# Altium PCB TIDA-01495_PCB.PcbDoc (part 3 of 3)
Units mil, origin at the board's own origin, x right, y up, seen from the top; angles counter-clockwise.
Board outline 7283.46 x 4330.71 mil, 2 copper layers (Top Layer, Bottom Layer), stack 64.6 mil thick; 242 components, 114 nets, 539 pads, 127 vias.
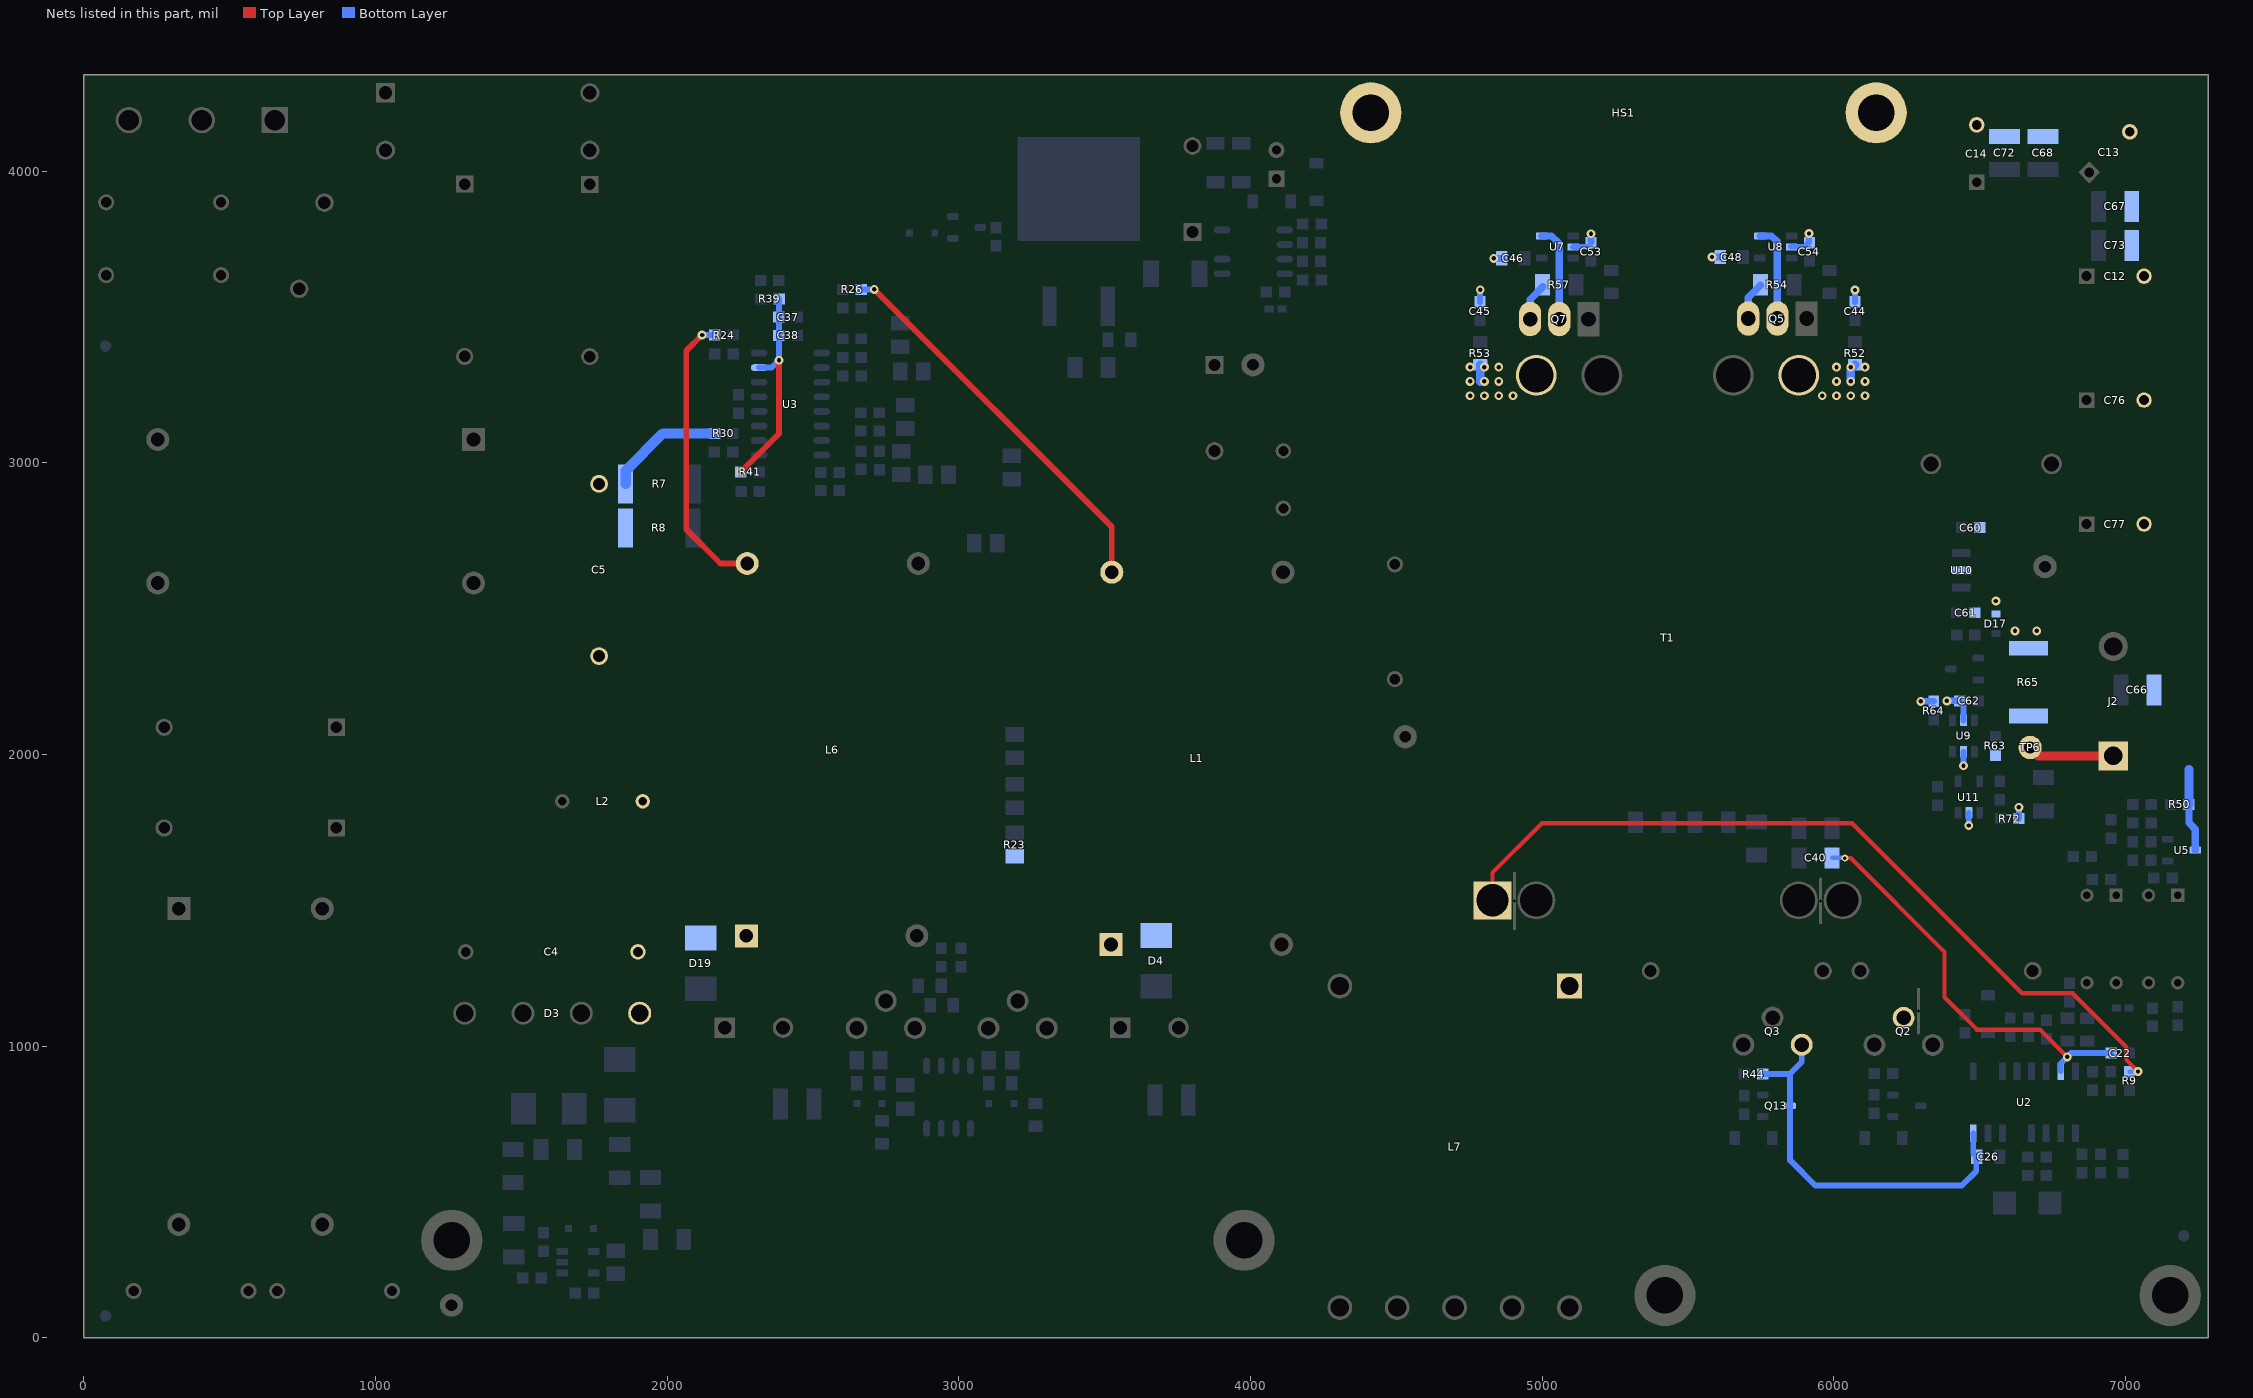
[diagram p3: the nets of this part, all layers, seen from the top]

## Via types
v1: diameter 30, hole 15, Top Layer to Bottom Layer, 109 vias
v2: diameter 20, hole 10, Top Layer to Bottom Layer, 16 vias
v3: diameter 24, hole 12, Top Layer to Bottom Layer, 2 vias

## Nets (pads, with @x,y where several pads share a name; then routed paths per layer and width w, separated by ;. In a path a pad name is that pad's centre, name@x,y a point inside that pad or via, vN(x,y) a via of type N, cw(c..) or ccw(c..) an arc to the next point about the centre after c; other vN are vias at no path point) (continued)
RET: J2.1 R63.1 R65.2 TP6.1 | length 297.1
  Top Layer w30: TP6.1@6672.83,2023.89 6701.72,1995 J2.1@6958,1995
SGND: C12.2 C13.2 C14.2 C44.1 C45.1 C46.2 C48.2 C53.2 C54.2 C60.2 C61.2 C62.2 C66.2 C67.2 C68.2 C72.2 C73.2 C76.2 C77.2 D17.2 HS1.1 HS1.2 Q5.3 Q7.3 R50.1 R54.2 R57.2 R64.1 R65.1 R72.1 U5.3 U7.2 U8.2 U9.2 U9.5 U10.2 U11.2 | length 1149.6
  Bottom Layer w20: v1(4787.47,3592.79) C45.1@4787.51,3551.52 ; U7.2@5106.37,3740.06 C53.2@5152.55,3740.06 ; U8.2@5853.68,3740.59 5899.86,3740.59 5914.92,3755.66 v1(5914.92,3785.88) ; C44.1@6072.63,3551.41 6072.78,3551.56 v1(6072.78,3592.14) ; v1(6444.73,1961.08) U9.2@6444.73,2009.36 ; v1(6462.82,1756.25) U11.2@6462.82,1799.63 ; R72.1@6634.5,1780 v1(6634.5,1819.4) ; C45.1@4787.51,3551.52 C45.1@4787.51,3551.52
  Bottom Layer w22: v1(6298.32,2181.88) R64.1@6342.6,2181.88 ; v1(6387.7,2183.57) C62.2@6432.04,2183.57 6444.73,2170.88 U9.5@6444.73,2117.63
  Bottom Layer w25: v1(4834.14,3700.57) C46.2@4862.03,3700.57 ; Q7.3@4958.88,3492.68 4958.88,3559.96 R57.2@5001.91,3603 ; C53.2@5167.61,3755.13 v1(5167.61,3785.35) ; v1(5582.5,3705.36) C48.2@5611.35,3705.36 ; Q5.3@5706.6,3494.47 5706.6,3566.62 R54.2@5748.88,3608.89 ; R50.1@7217.57,1828.83 7217.57,1765.55 7239.24,1743.87 U5.3@7239.24,1672
  Bottom Layer w30: R50.1@7217.57,1828.83 7217.57,1948.79
  other v1: 6620.98,2423.54 6695.53,2423.54 6555.7,2526.27
SW: C26.2 L7.1 Q2.2 Q3.3 Q13.3 R44.1 U2.16 | length 1330.1
  Bottom Layer w20: R44.1@5756.43,905.97 R44.1@5756.5,905.97 ; R44.1@5756.5,904 5848.22,904 5850.18,905.96 ; Q3.3@5890,1005 5890,945.78 5850.18,905.96 ; U2.16@6477.97,701.33 6477.97,632.66 C26.2@6489.63,621 ; C26.2@6488.2,614.43 6488.2,571.44 6438.71,521.95 5936.66,521.95 5850.18,608.43 Q13.3@5850.18,795.57 5850.18,905.96
VAC: C5.2 D4.2 D19.2 L1.1 L2.2 L6.1 R23.2
VCR: C22.1 C40.2 U2.7 | length 1393.6
  Top Layer w15: v3(6037.56,1645) 6057.67,1645 6379.61,1323.07 6379.61,1167.68 6490.56,1056.72 6706.97,1056.72 v1(6800.67,963.02)
  Bottom Layer w15: C40.2@5994.36,1645.3 6037.27,1645.3 v3(6037.56,1645)
  Bottom Layer w20: U2.7@6777.97,913.93 6777.97,940.32 v1(6800.67,963.02) 6813.65,976 C22.1@6950.5,976
VD1: Q7.2 R53.1 T1.13 U7.5 | length 385.9
  Bottom Layer w25: U7.5@4998.1,3777.47 5031.88,3777.47 5058.88,3750.48 Q7.2@5058.88,3492.68
  Bottom Layer w30: v1@4787.47,3278.79 4787.47,3334.91 R53.1@4787.51,3334.95
  other v1: 4753,3230 4802,3230 4851,3230 4900,3230 4753,3279 4802,3279 4851,3279 4753,3328 4802,3328 4851,3328
VD2: Q5.2 R52.1 T1.8 U8.5 | length 393.7
  Bottom Layer w20: Q5.2@5806.19,3493.21 Q5.2@5806.19,3493.36
  Bottom Layer w25: U8.5@5746.87,3777.4 5786.04,3777.4 5806.19,3757.25 Q5.2@5806.19,3493.36
  Bottom Layer w30: v1(6058,3279) 6058,3319.93 6072.78,3334.7 R52.1@6072.63,3334.85
  other v1: 5960,3230 6009,3230 6058,3230 6107,3230 6009,3279 6107,3279 6009,3328 6058,3328 6107,3328
VN: C4.2 C5.1 D3.4 R7.2 R8.2 R30.1 | length 403.4
  Bottom Layer w35: R7.2@1858.08,2927.3 1858.08,2973.24 1985.64,3100.8 R30.1@2162.72,3100.8
VREF: C37.1 C38.1 R39.1 R41.2 U3.15 | length 726.5
  Top Layer w20: v1(2252.82,2968.64) 2383.68,3099.5 v1(2383.68,3351.71)
  Bottom Layer w20: U3.15@2315.54,3326.17 2358.14,3326.17 v1(2383.68,3351.71) C38.1@2383.68,3436.5 C37.1@2383.68,3499.14 2383.95,3499.41 R39.1@2383.95,3562.07
X: R9.2 T1.1 | length 2785.3
  Top Layer w15: T1.1@4830,1500 4830,1594.87 4999.22,1764.08 6062.57,1764.08 6645.41,1181.24 6818.51,1181.24 7003.61,996.14 7003.61,952.39 v1(7043,913)
  Bottom Layer w15: R9.2@7014.06,912.54 7014.51,913 v1(7043,913)
ZCD1: L1.4 R26.2 | length 1351.8
  Top Layer w20: v1(2710.66,3594.32) 3524.65,2780.34 L1.4@3524.65,2624.76
  Bottom Layer w20: R26.2@2665.62,3594.32 v1(2710.66,3594.32)
ZCD2: L6.4 R24.1 | length 989.7
  Top Layer w20: v1(2120,3438) 2065.75,3383.75 2065.75,2771.79 2182.78,2654.76 L6.4@2274.65,2654.76
  Bottom Layer w20: v1(2120,3438) 2163.63,3438 R24.1@2163.67,3437.96
pads on no net: FID1.1 FID2.1 FID3.1 H1.0 H2.0 H3.0 H4.0 H5.0 H6.0 HS3.1 HS3.2 L7.6 L7.7 L7.8 L7.9 L7.10 U1.1 U1.8 U4.6

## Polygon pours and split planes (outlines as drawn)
PGND on Bottom Layer "Bottom Layer-NetC3_1" (solid, remove dead copper, pour order 320): 1153.7,435.61 1153.7,122.84 1206.84,69.7 1696.94,69.7 1724.67,97.43 1724.67,409.73 1686.47,447.94 1164.06,447.94 1153.71,437.58
RET on Bottom Layer "RET_L02_P318" (solid, remove dead copper, pour order 318): 6531.16,2011.21 6531.16,2015.91 6536.88,2021.63 6586.95,2021.63 6599.05,2033.73 6599.05,2158.74 6602.41,2162.1 6739.52,2162.1 6741.87,2159.75 6741.87,1991.38 6732.46,1981.97 6581.32,1981.97 6574.93,1975.59 6535.66,1975.59 6531.09,1980.15
SGND on Bottom Layer "SGND_L02_P316" (solid, remove dead copper, pour order 316): 6477.33,2794.24 6477.33,2662.33 6465,2650 6406.96,2650 6402.27,2645.31 6402.27,2614.25 6407.22,2609.3 6463.63,2609.3 6484.4,2588.52 6484.4,2535.86 6461.56,2513.02 6461.56,2464.49 6466.62,2459.43 6580.78,2459.43 6596.57,2443.64 6596.57,2296.67 6609.16,2284.08 6739.23,2284.08 6754.49,2299.34 6754.49,2392.65 6639.68,2507.46 6639.68,2785.64 6623.72,2801.6 6481.27,2801.6 6477.32,2797.65
PGND on Bottom Layer "PGND_L02_P276" (solid, remove dead copper, pour order 276): 3879.97,749.02 3762.75,749.02 3757.65,754.12 3756.08,755.69 3756.08,798.07 3756.08,876.55 3758.82,879.3 3765.49,885.97 3809.44,885.97 3876.95,885.97 3896.5,866.42 3896.5,765.54
PGND on Bottom Layer "PGND_L02_P274" (solid, remove dead copper, pour order 274): 2596.98,736.94 2479.76,736.94 2474.66,742.05 2473.09,743.61 2473.09,786 2473.09,864.48 2475.84,867.23 2482.51,873.9 2526.46,873.9 2593.96,873.9 2613.51,854.35 2613.51,753.47
VN on Bottom Layer "Bottom Layer-No Net 8" (solid, remove dead copper, pour order 268): 1731.09,2748.63 1778.3,2701.43 1882.01,2701.43 1891.98,2711.4 1891.98,2994.62 1885.33,3001.27 1758.35,3001.27 1731.09,2974.01
VAC on Bottom Layer "Bottom Layer-No Net 7" (solid, remove dead copper, pour order 266): 3533.76,1458.24 3562.13,1429.86 3721.99,1429.86 3730.37,1421.48 3730.37,1337.98 3727.32,1334.93 3592.51,1334.93 3568.08,1310.5 3562.38,1304.8 3465.47,1304.8 3275.25,1495.03 2472.42,1495.03 2300.65,1323.26 2052.66,1323.26 2030.88,1345.03 2030.88,1528.98 2015.79,1544.67 1886.39,1674.07 1886.39,2088.71 1733.37,2241.73 1733.37,2352.73 1752.26,2371.62 1859.32,2371.62 2049.66,2181.28 2049.66,1834.23 2202.54,1681.35 3310.65,1681.35 3485.79,1506.21
NetC6_1 on Bottom Layer "Bottom Layer-No Net 4" (solid, remove dead copper, pour order 256): 483.99,3812.17 1313.76,3812.17 1421.68,3704.24 1421.68,3302.5 1292.86,3173.67 1292.86,3037.85 1301.7,3029.01 1421.68,3029.01 1617.39,3224.71 1617.39,3617.05 1771.61,3771.27 1771.61,4091.38 1755.7,4107.29 1388.89,4107.29 1258.82,3977.22 480.24,3977.22 440.1,3937.07 440.1,3856.06
24V on Bottom Layer "Bottom Layer-No Net 3" (solid, remove dead copper, pour order 242): 6795.38,2285.4 6795.38,2402.09 6670.78,2525.96 6670.78,3111.21 6811.03,3251.45 6917.09,3251.45 6949.11,3219.43 6949.11,2552.23 7028.96,2472.38 7028.96,2166.11 7017.9,2155.04 6925.74,2155.04
NetC8_1 on Bottom Layer "Bottom Layer-No Net 2" (solid, remove dead copper, pour order 240): 5359.75,3356.39 5173.85,3356.39 5129.91,3312.45 5129.91,2624.39 5132.45,2621.85 6316.47,2621.85 6625.84,2931.22 6625.84,3161.31 6944.07,3479.54 6944.07,4013.91 6909.58,4048.4 6455.14,4048.4 6220.2,3813.45 6220.2,3267.44 6110.06,3157.31 5781.01,3157.31 5731.01,3207.3 5731.01,3324.27 5698.82,3356.47 5360.24,3356.47
SGND on Bottom Layer "Bottom Layer-No Net 1" (solid, remove dead copper, pour order 228): 7067.38,1904.19 7091.81,1879.76 7264.07,1879.76 7283.65,1899.34 7283.13,1950.89 7283.13,4253.01 7207.24,4328.9 6068.88,4328.9 6029.07,4289.09 6029.05,4231.23 6029.05,4124.1 6072.32,4080.83 6935.53,4080.83 6989.1,4027.27 6989.1,2581.03 7067.38,2502.74
NetC47_1 on Bottom Layer "Bottom Layer-No Net" (solid, remove dead copper, pour order 216): 1088.75,486.2 1312.06,709.51 1537.82,709.51 1574.1,745.79 1574.1,1104.13 1524.14,1154.09 1488.08,1154.09 1446.44,1112.44 1446.44,968.21 1400.79,922.56 1208.11,922.56 774.56,489.01 774.56,371.88 1017.44,129.01 1067.18,129.01 1088.75,150.58
390V on Bottom Layer "Bottom Layer-No Net 9" (solid, remove dead copper, pour order 282): 3641.27,1270.92 3617.4,1247.04 3431.44,1061.08 3431.44,634.94 3355.4,558.9 2364.26,558.9 2232.67,690.49 2232.67,1098.37 2232.67,1222.65 2213.21,1242.12 2061.08,1242.12 2055.54,1236.57 2055.54,1091.81 2099.9,1047.45 2099.9,516.16 2429.91,186.15 3345.37,186.15 3582.24,423.02 3582.24,1027.05 3713.36,1158.17 3886.54,1158.17 3956.45,1227.46 3956.45,1736.68 3867.72,1825.41 3867.72,3102.01 3943.54,3177.82 3943.54,3343.41 3918.65,3368.29 3715.05,3368.29 3665,3318.24 3665,3064.87 3665,1726.4 3711.91,1679.5 3791.78,1599.62 3791.78,1279.66 3783.03,1270.92
PGND on Bottom Layer "Bottom Layer-No Net 10" (solid, remove dead copper, pour order 284): 6301.05,1021.31 6301.05,1029.05 6308.73,1036.73 6308.73,1201.75 6301.05,1209.43 6301.05,1306.5 6263.09,1344.46 6092.26,1344.46 5968.34,1468.38 5968.34,1531.73 6008.03,1571.42 6341.73,1571.42 6641.94,1269.61 6708.92,1269.61 6738.53,1240.01 6879.52,1240.01 6921.62,1197.9 6921.62,1081.6 6912.72,1072.69 6422.53,1072.69 6380.21,1030.38 6380.21,966.2 6357.38,943.37 6321.8,943.37 6301.05,964.12
PGND on Bottom Layer "PGND_L02_P286" (solid, remove dead copper, pour order 286): 2040.66,3624.28 2040.66,2977.46 2040.66,2707.35 2117.46,2630.54 2155.86,2592.14 2578.29,2592.14 3016.72,2592.14 3452.92,3028.34 3452.92,3612.39 3384.19,3681.12 2243.64,3681.12 2097.49,3681.12
390V on Bottom Layer "Bottom Layer-No Net 11" (solid, remove dead copper, pour order 288): 5727,1108.05 5774.77,1060.28 5806.27,1060.28 5827.74,1081.75 5827.74,1138.09 5069.05,1896.79 3894,1896.79 3840.46,1950.33 3840.46,1671.63 3893.29,1724.46 4979.51,1724.46 5340.65,1363.32 5340.65,1218.32 5450.93,1108.05
NetL7_2 on Bottom Layer "Bottom Layer-No Net 12" (solid, remove dead copper, pour order 300): 4254.1,1183.76 4291.63,1146.23 4827.86,1146.23 5052.01,1370.37 5052.01,1521.68 5007.16,1566.53 4953.63,1566.53 4913.66,1526.56 4913.66,1389.5 4811.94,1287.79 4290.56,1287.79 4254.1,1251.33
PGND on Bottom Layer "Bottom Layer-No Net 13" (solid, remove dead copper, pour order 302): 6646.3,1246.35 6646.3,765.55 6940.21,471.64 7126.86,471.64 7178.95,523.73 7178.95,1163.79 7102.53,1240.21 7100.11,1240.21 6719.75,1240.21 6699.11,1260.85 6655.11,1260.85
NetC2_2 on Bottom Layer "Top Layer-No Net 11" (solid, remove dead copper, pour order 298): 6122.95,1229.95 6117.43,1224.44 5924.56,1224.44 5810.84,1338.16 5810.84,1510.21 5811.61,1541.21 5837.96,1567.56 5909.26,1567.56 5940.99,1535.84 5940.99,1411.92 6063.36,1289.55 6113.74,1289.55 6122.95,1280.33 6122.95,1244.74
VD1 on Bottom Layer "Top Layer-No Net 3" (solid, remove dead copper, pour order 322): 5017.39,3502.9 5017.39,3433.59 4944.13,3360.33 4757.56,3360.33 4733.01,3335.79 4733.01,3218.48 4769.27,3182.22 5051.87,3182.22 5103.59,3233.94 5103.59,3527.93 5078.18,3553.34 5038.73,3553.34 5017.39,3532
VD2 on Bottom Layer "Top Layer-No Net 3" (solid, remove dead copper, pour order 324): 5846.27,3431.8 5917.33,3360.73 6101.17,3360.73 6125.09,3336.82 6125.09,3220.77 6088.33,3184.01 5869.93,3184.01 5813.61,3184.01 5766.58,3231.03 5766.58,3531.36 5790.36,3555.13 5823.26,3555.13 5846.27,3532.12
NetD5_3 on Top Layer "Top Layer-No Net 9" (solid, remove dead copper, pour order 264): 2689.43,1161.85 2734.12,1117.17 2765.28,1117.17 2897.57,1249.46 2897.57,1265.96 2897.57,1396.13 2873.73,1419.97 2515.52,1419.97 2361.51,1265.96 2361.51,1048.12 2382.85,1026.77 2414,1026.77 2549.08,1161.85
NetD1_3 on Top Layer "Bottom Layer-No Net 6" (solid, pour order 262): 3307.74,1157.15 3257.44,1157.15 3217.25,1116.96 3186.26,1116.96 3163.69,1139.53 3163.69,1198.21 3186.18,1220.7 3231.42,1265.94 3606.23,1265.94 3729.15,1388.86 4128.32,1388.86 4149.8,1367.38 4149.79,1333.56 3843.73,1027.49 3739.08,1027.49 3609.42,1157.15
NetC4_1 on Top Layer "Top Layer-No Net 8" (solid, remove dead copper, pour order 260): 1237.75,1092.8 1268.37,1062.18 1344.19,1062.18 1379.57,1097.56 1379.57,1418.84 1675.77,1715.04 1675.77,1841.33 1652.25,1864.85 1590.93,1864.85 1237.75,1511.67
VN on Top Layer "Bottom Layer-No Net 5" (solid, remove dead copper, pour order 258): 1851.48,1106.64 1886.56,1071.56 1992.2,1071.56 2031.32,1110.68 2031.32,1460.68 2219.98,1649.34 2219.98,2381.87 1920.77,2681.08 1920.77,2918.91 1880.88,2958.8 1754.27,2958.8 1731.56,2936.08 1731.56,2609.92 2031.32,2310.16 2031.32,1736.58 1851.49,1556.75
NetC9_2 on Top Layer "Top Layer-No Net 6" (solid, remove dead copper, pour order 252): 216.79,4056.19 216.79,3776.87 695.03,3298.63 1460.84,3298.63 1492.1,3267.37 1492.1,3031.16 1273.3,2812.35 1273.3,2560.95 1310.81,2523.44 1410.83,2523.44 1448.34,2560.95 1448.34,2787.8 1789.05,3128.51 1789.05,3398.65 1751.54,3436.16 949.86,3436.16 721.68,3664.34 526.24,3664.34 376.21,3814.38 376.21,3998.02 455.13,4076.94 455.13,4193.74 427.29,4221.58 382.19,4221.58
NetFCL1_1 on Top Layer "Top Layer-No Net 5" (solid, remove dead copper, pour order 248): 605.98,4211.74 605.98,4095.32 671.21,4030.08 1089.73,4030.08 1140.91,4081.27 1140.91,4271.96 1099.76,4313.1 625.41,4313.1 605.91,4293.61
NetC10_1 on Top Layer "Top Layer-No Net 4" (solid, remove dead copper, pour order 246): 745.75,2449.76 745.75,1472.58 789.13,1429.19 853.75,1429.19 917.55,1493 917.55,2552.15 334.95,3134.75 231.77,3134.75 195.6,3098.58 195.6,2999.91 244.93,2950.58
NetC10_2 on Top Layer "Top Layer-No Net 1" (solid, remove dead copper, pour order 244): 187.75,2609.23 187.75,1479.6 238.07,1429.29 367.6,1429.29 406.89,1468.58 406.89,2510.41 277.68,2639.63 218.15,2639.63
VD2 on Top Layer "Top Layer-No Net 3" (solid, remove dead copper, pour order 238): 5846.27,3431.8 5917.33,3360.73 6101.3,3360.73 6125.09,3336.94 6125.09,3221.03 6088.07,3184.01 5869.93,3184.01 5813.61,3184.01 5766.58,3231.03 5766.58,3531.36 5790.36,3555.13 5823.26,3555.13 5846.27,3532.12
VD1 on Top Layer "Top Layer-No Net 3" (solid, remove dead copper, pour order 236): 5017.39,3502.9 5017.39,3433.59 4944.13,3360.33 4757.52,3360.33 4733.1,3335.91 4733.1,3218.53 4769.41,3182.22 5051.87,3182.22 5103.59,3233.94 5103.59,3527.93 5078.18,3553.34 5038.73,3553.34 5017.39,3532
NetC49_2 on Top Layer "Top Layer-No Net" (solid, remove dead copper, pour order 214): 140.93,312.79 140.93,148.19 158.83,130.29 182.44,130.29 275.76,223.6 767.7,715.54 1597.64,715.54 1749.17,867.07 1749.17,1129.92 1725.26,1153.83 1687.08,1153.83 1663.18,1129.94 1663.18,1011.05 1538.22,886.09 714.22,886.09
SW on Top Layer "Top Layer-No Net 10" (solid, remove dead copper, pour order 280): 5802.18,751.68 5928.22,877.72 5928.22,996.62 6046.17,1114.57 6168.64,1114.57 6223.65,1059.56 6255.74,1059.56 6277.57,1081.24 6277.57,1123.93 6233.5,1168 5999.77,1168 5851.86,1020.09 5851.86,1007.55 5851.86,944.96 5811.63,904.73 5534.96,904.73 5182.31,1257.38 5052.48,1257.38 5041.46,1246.36 5041.65,1179.37 5041.65,913.31 5203.28,751.68
PGND on Top Layer "Top Layer-No Net 12" (solid, remove dead copper, pour order 294): 7077.3,1265.07 7047.68,1294.69 6425.04,1294.69 6339.7,1209.36 6339.7,1062.12 6301.12,1023.54 6301.12,860.08 6025.57,584.53 5230.32,584.53 4869.6,945.25 3483.31,945.25 3329.02,1099.7 3285.77,1099.7 3264.3,1078.23 3264.3,1006.13 3226.71,968.54 3070.02,968.54 2915.55,1123.01 2857.45,1123.01 2812.05,1077.61 2812.05,992.1 2774.59,954.64 2089.09,954.64 1580.57,446.13 1219.07,446.13 1144.77,371.83 1144.77,126.5 1271.28,-0.01 6822.81,-0.01 7178.88,356.06 7178.88,1163.5
PGND on Top Layer "Top Layer-No Net 13" (solid, pour order 296): 4350.39,904.42 4463.1,1017.13 4463.1,1252.41 2864.91,2850.6 2146.95,2850.6 2101.27,2896.29 2101.27,3517.46 2289.24,3705.43 3353.97,3705.43 3514.08,3545.31 3514.08,3106.28 3648.38,2971.98 4059.01,2971.98 4730.53,2300.46 4730.53,1082.54 4906.45,906.62
SGND on Top Layer "Top Layer-No Net 2" (solid, remove dead copper, pour order 312): 6278.36,2584.14 6186.63,2492.4 6186.63,2003.62 6453.48,1736.76 7206.08,1736.76 7278.74,1809.42 7278.74,1824.23 7282.62,1824.23 7282.62,2467.79 7263.07,2487.34 7273.1,2497.37 7273.31,2736.59 7273.54,4290.83 7234.79,4329.57 4390.66,4329.57 4306.64,4245.56 4306.64,3921.82 4796.58,3431.88 4975.07,3431.88 4998.75,3455.57 4998.75,3545.55 5029.63,3576.42 5308.2,3576.42 5452.74,3431.88 5724.72,3431.88 5748.17,3455.32 5748.17,3555.95 5768.64,3576.42 6153.54,3576.42 6750.68,3576.42 6907.78,3419.32 6907.78,2752.8 6907.78,2658.55 6833.37,2584.14

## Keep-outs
Keep-Out Layer:
  circle w6: c2748.54,396.21 r80.51
  circle w6: c3200.55,396.21 r80.51
  circle w6: c5788.79,339.36 r80.51
  circle w6: c6237.55,339.14 r80.51
  circle w6: c5807.81,4160.11 r80.51
  circle w6: c5060.08,4158.33 r80.51
  lines w10: 0,0 0,4330.71 7283.46,4330.71 7283.46,0 0,0
  text ".Layer_Name" at 441.79,-892.66 h60

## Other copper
Top Layer:
  rectangle net NetC6_1: 1635.6,3913.99 1840,4312.79
  text ".Layer_Name" at 441.79,-892.66 h60
Bottom Layer:
  pour cut-out: 3949.37,3224.93 3913.56,3224.93 3772.18,3083.55 3772.18,2984.4 3896.12,2860.47 3921.82,2860.47 3971.46,2910.1 3971.46,3214.56 3960.96,3225.07 3952.62,3225.07
  text ".Layer_Name" at 441.79,-892.66 h60

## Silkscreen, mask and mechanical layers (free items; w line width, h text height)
Top Overlay:
  text "TIDA-01495-E1" at 4574.04,2699.95 h125 r90
  text ".Layer_Name" at 441.79,-892.66 h60
Bottom Overlay:
  lines w6: 1564.84,146.84 1589.87,146.84 1633.99,190.96 ; 2337.87,3358.12 2415,3358.12 ; 2594.85,3631.63 2594.85,3796.06 2636.19,3837.41 2675.66,3837.41 ; 2636.49,3258.56 2706.31,3258.56 ; 2704.09,3327.39 2742.42,3365.73 2742.42,3625.42 ; 4281.03,3767.99 4340.42,3767.99 4355.18,3753.22 ; 6602.35,1869.77 6626.43,1869.77 ; 6741.97,974.75 6758.78,974.75 6772.93,988.91 ; 6916.94,1538.35 6916.94,1492.12 ; 6979.18,1631.55 6943.75,1631.55 6923.08,1610.89 6790.21,1610.89 6769.95,1610.89 ; 7125.79,1540.7 7125.79,1487.84 ; 6769.95,1610.89 6769.95,1608.58 6776.62,1601.91 6776.62,1617.55 6769.95,1610.89 ; 6916.94,1492.12 6924.32,1499.5 6909.17,1499.5 6916.55,1492.12 6916.94,1492.12 ; 7125.79,1487.84 7125.79,1488.37 7132.22,1494.8 7118.83,1494.8 7125.79,1487.84
  text ".Layer_Name" at 441.79,-892.66 h60
Top Paste:
  text ".Layer_Name" at 441.79,-892.66 h60
Bottom Paste:
  text ".Layer_Name" at 441.79,-892.66 h60
Top Solder:
  text ".Layer_Name" at 441.79,-892.66 h60
  text ".Layer_Name" at 441.79,-892.66 h60
Bottom Solder:
  text ".Layer_Name" at 441.79,-892.66 h60
Drill Guide:
  text ".Layer_Name" at 441.79,-892.66 h60
M1 Board Outline:
  the board outline again, w10
M2 Board Dimensions:
  rectangle: -10.21,-434.17 364.79,-309.17
  rectangle: -135.21,-309.17 -10.21,-184.17
  lines w7: -135.21,-309.17 864.79,-309.17 ; -10.21,-434.17 -10.21,-184.17 ; 114.79,-434.17 114.79,-184.17 ; 364.79,-434.17 364.79,-184.17 ; 614.79,-434.17 614.79,-184.17 ; -135.21,-434.17 -135.21,-184.17 864.79,-184.17 864.79,-434.17 -135.21,-434.17
M3 3D STEP Top:
  text ".Layer_Name" at 441.79,-892.66 h60
M4 3D STEP Bottom:
  text ".Layer_Name" at 441.79,-892.66 h60
M5 Assembly Top:
  lines w10: -427.21,-964.33 6172.79,-964.33 ; -427.21,-761 6174.79,-761 ; -427.21,-557.67 -427.21,-1167.67 3577.79,-1167.67 6174.79,-1167.67 6174.79,-557.67 -426.71,-557.67 -426.71,-1167.67 1148.79,-1167.67 ; 2037.79,-1167.67 2037.79,-557.67 ; 3304.79,-761 3304.79,-557.67 ; 4144.79,-761 4144.79,-557.67 ; 4766.79,-1174.17 4766.79,-971.33
  text "COMPONENTS MARKED 'DNP' SHOULD NOT BE POPULATED." at 1018.29,-352.67 h60
  text "ASSEMBLY VARIANT:" at 1017.79,-468.17 h60
  text ".VariantName" at 2053.79,-468.17 h60
  text "PCB VIEWED FROM TOP SIDE" at -363.71,-689.83 h60
  text "BOARD #:" at 2112.79,-689.83 h60
  text ".PRJ_Number" at 2658.29,-689.83 h60
  text "REV:" at 3502.79,-689.83 h60
  text ".PCB_Rev" at 3794.29,-689.83 h60
  text "SVN REV:" at 4340.79,-689.83 h60
  text ".VersionControl_RevNumber" at 4846.79,-689.83 h60
  text "LAYER NAME =" at -363.71,-892.66 h60
  text "TID #:" at 2112.79,-893.17 h60
  text ".TID" at 2658.29,-893.17 h60
  text ".layer_Name" at 432.79,-895.17 h60
  text "PLOT NAME =" at -363.71,-1098.5 h60
  text ".plot_File_Name" at 441.79,-1098.5 h60
  text "GENERATED    :" at 2114.79,-1098.5 h60
  text ".Print_Date" at 2984.29,-1098.5 h60
  text ".Print_Time" at 3713.29,-1098.5 h60
  text "TEXAS INSTRUMENTS" at 4977.79,-1098.5 h60
M6 Assembly Bottom:
  lines w10: -427.71,-761.5 6174.29,-761.5 ; -425.71,-964.83 6174.29,-964.83 ; 980.29,-1174.67 980.29,-971.83 ; 1602.29,-761.5 1602.29,-558.17 ; 2442.29,-761.5 2442.29,-558.17 ; 3709.29,-1168.17 3709.29,-558.17 ; 4598.29,-1168.17 6173.79,-1168.17 6173.79,-558.17 -427.71,-558.17 -427.71,-1168.17 2169.29,-1168.17 6174.29,-1168.17 6174.29,-558.17
  text "COMPONENTS MARKED 'DNP' SHOULD NOT BE POPULATED." at 5966.79,-352.17 h60
  text ".VariantName" at 4922.79,-468.17 h60
  text "ASSEMBLY VARIANT:" at 5961.79,-468.17 h60
  text ".VersionControl_RevNumber" at 900.29,-690.33 h60
  text "SVN REV:" at 1406.29,-690.33 h60
  text ".PCB_Rev" at 1952.79,-690.33 h60
  text "REV:" at 2244.29,-690.33 h60
  text ".PRJ_Number" at 3088.79,-690.33 h60
  text "BOARD #:" at 3634.29,-690.33 h60
  text "PCB VIEWED FROM BOTTOM SIDE" at 6110.79,-690.33 h60
  text "LAYER NAME =" at 6110.79,-886.57 h60
  text ".TID" at 3088.79,-893.67 h60
  text "TID #:" at 3634.29,-893.67 h60
  text ".layer_Name" at 5288.79,-895.17 h60
  text "TEXAS INSTRUMENTS" at 769.29,-1099 h60
  text ".Print_Time" at 2033.79,-1099 h60
  text ".Print_Date" at 2762.79,-1099 h60
  text "GENERATED    :" at 3632.29,-1099 h60
  text ".plot_File_Name" at 5305.29,-1099 h60
  text "PLOT NAME =" at 6110.79,-1099 h60
M9 Title Sheet:
  drawing of 57 lines, arcs and shapes, not listed
  text "1" at 604.63,8002.33 h70
  text "2" at 3100.29,8002.33 h70
  text "3" at 5589.64,8002.33 h70
  text "4" at 8096.3,8002.33 h70
  text "5" at 10595.29,8002.33 h70
  text "6" at 13100.29,8002.33 h70
  text "A" at -551.71,6859.33 h70
  text "A" at 14248.29,6859.33 h70
  text "B" at -551.71,4479.33 h70
  text "B" at 14248.29,4479.33 h70
  text "C" at -551.71,2104.33 h70
  text "C" at 14248.29,2104.33 h70
  text "PROJECT TITLE:" at 11208.29,243.33 h45
  text ".PRJ_Title" at 11258.29,110.01 h60
  text "DESIGNED FOR:" at 11208.29,-57.67 h45
  text ".PRJ_Customer" at 11258.29,-197.67 h70
  text "D" at -551.71,-265.67 h70
  text "D" at 14248.29,-265.67 h70
  text "FILE NAME:" at 11208.29,-357.67 h45
  text ".PCB_File_Name_No_Path" at 11258.29,-477.67 h70
  text "Texas Instruments (TI) and/or its licensors do not warrant the accuracy or completeness of this specification" at 6238.79,-639.5 h45
  text "ENGINEER:" at 11208.29,-647.67 h45
  text "LAYOUT BY:" at 12713.29,-647.67 h45
  text "or any information contained therein. TI and/or its licensors do not warrant that this design will meet" at 6193.81,-752.17 h45
  text ".PRJ_Engineer" at 11258.29,-802.66 h70
  text ".PCB_Layout" at 12763.79,-802.66 h70
  text "the specifications, will be suitable for your application or fit for any particular purpose, or will operate in" at 6193.81,-864.84 h45
  text "ALTIUM DESIGNER VERSION:" at 12713.29,-957.67 h45
  text "an implementation. TI and/or its licensors do not warrant that the design is production worthy. You should" at 6193.81,-977.5 h45
  text "completely validate and test your design implementation to confirm the system functionality for your application." at 6238.79,-1090.17 h45
  text ".print_Scale" at 11258.29,-1090.99 h70
  text ".Application_BuildNumber" at 12763.79,-1090.99 h70
  text "1" at 604.63,-1297.67 h70
  text "2" at 3100.29,-1297.67 h70
  text "3" at 5589.64,-1297.67 h70
  text "4" at 8096.3,-1297.67 h70
  text "5" at 10595.29,-1297.67 h70
  text "6" at 13100.29,-1297.67 h70
M10 Fab Notes:
  drawing of 191 lines, arcs and shapes, not listed
  text "DESIGN INFORMATION" at 12251.81,6651.83 h60
  text "(REFER ALSO ARRAY/PANEL PROFILING INFORMATION)" at 11890.25,6490.12 h60
  text "BOARD SIZE" at 11204.25,6485.83 h60
  text "X" at 12172.25,6358.01 h60
  text "110MM" at 12407.79,6350.83 h60
  text "185MM" at 11720.29,6347.35 h60
  text "Number of Layers :" at 11622.25,6250.83 h60
  text "2" at 12717.06,6240.84 h60
  text "MIN. TRACK WIDTH:" at 11622.25,6111.83 h60
  text "10" at 12691.79,6112.23 h60
  text "MIL" at 12873.25,6111.83 h60
  text "5" at 12702.68,5986.33 h60
  text "MIN. CLEARANCE:" at 11622.25,5979.83 h60
  text "MIL" at 12890.79,5953.23 h60
  text "MIN. VIA PAD SIZE:" at 11622.25,5847.83 h60
  text "19.69" at 12599.79,5841.83 h60
  text "MIL" at 12890.79,5825.23 h60
  text "0.15mm (5.91MIL)" at 12317.25,5706.12 h60
  text "EXTERNAL" at 13053.79,5706.23 h60
  text "MINIMUM ANNULAR RING" at 11293.02,5701.84 h60
  text "PER" at 11493.02,5583.84 h60
  text "IPC-D-275 CLASS 2 LEVEL C" at 11713.02,5583.83 h60
  text "MIL, HOLES" at 13201.25,5471.55 h60
  text "+/-" at 12808.79,5470.84 h60
  text "+/-" at 13662.79,5470.84 h60
  text "REGISTRATION TOLERANCES:" at 11293.02,5465.83 h60
  text "METAL" at 12492.79,5465.83 h60
  text "5" at 13068.99,5465.84 h60
  text "3" at 13901.99,5465.84 h60
  text "MIL" at 14018.25,5465.83 h60
  text "IMPEDENCE CONTROLLED BOARD:NO" at 11325.79,5316.83 h60
  text "MATERIAL:" at 11202.25,5093.38 h60
  text "FR-4 High Tg" at 12188.7,4953.04 h60
  text "FR-408" at 11623.25,4944.47 h60
  text "OTHER" at 13111.25,4944.47 h60
  text "X" at 12026.79,4942.83 h60
  text "THICKNESS:" at 11203.79,4787.83 h60
  text "63 MIL (1.6mm) +/-10%" at 11862.79,4782.83 h60
  text "OTHER" at 13228.25,4777.47 h60
  text "X" at 11727.79,4774.83 h60
  text "TOLERANCE:" at 11277.02,4619.47 h60
  text "X" at 12116.33,4619.47 h60
  text "ANSI IPC-6012 TYPE 3 CLASS 2" at 12303.27,4619.47 h60
  text "OTHER +/-" at 12303.25,4463.47 h60
  text "BOW & TWIST:" at 11277.02,4306.47 h60
  text "X" at 12116.33,4306.47 h60
  text "ANSI IPC-6012 TYPE 3 CLASS 2" at 12303.27,4306.47 h60
  text "OTHER +/-" at 12303.25,4147.97 h60
  text "DRILLING:" at 11202.25,4009.47 h60
  text "REFERENCE:" at 11277.02,3892.47 h60
  text "X" at 11925.25,3892.47 h60
  text "AS SHOWN" at 12112.25,3892.47 h60
  text "X" at 12826.25,3892.47 h60
  text "NC_DRILL FILES" at 12963.25,3892.47 h60
  text "PTH MIN COPPER THICKNESS:" at 11277.02,3734.47 h60
  text "X" at 12627.25,3734.47 h60
  text "1MIL" at 12764.25,3734.47 h60
  text "OTHER" at 13261.25,3734.47 h60
  text "BOARD FINISH:" at 11202.25,3575.47 h60
  text "SILKSCREEN:" at 11357.47,3457.47 h60
  text "X" at 12306.25,3457.47 h60
  text "TOP" at 12432.25,3457.47 h60
  text "BOTTOM" at 12943.25,3457.47 h60
  text "SILKSCREEN COLOR:" at 11357.47,3290.47 h60
  text "X" at 12305.21,3290.47 h60
  text "WHITE" at 12432.25,3290.47 h60
  text "OTHER" at 12943.25,3290.47 h60
  text "SOLDER RESIST COLOR:" at 11357.47,3120.47 h60
  text "X" at 11925.21,2961.28 h60
  text "GREEN" at 12052.25,2961.28 h60
  text "BLUE" at 12643.25,2961.28 h60
  text "OTHER" at 13181.25,2961.28 h60
  text "IMMERSION GOLD (ENIG)" at 12263.25,2772.76 h60
  text "ENEPIG" at 13600.79,2769.47 h60
  text "SURFACE FINISH:" at 11202.25,2768.47 h60
  text "X" at 12076.31,2768.47 h60
  text "IMM. TIN/SILVER OR EQUIV" at 11531.79,2611.47 h60
  text "OTHER" at 12963.25,2611.47 h60
  text "ARRAY/PANEL:" at 11202.25,2432.47 h60
  text "X" at 12067.2,2432.73 h60
  text "CUT AND TRIM PER MECH LAYER 1" at 12263.25,2428.19 h60
  text "N.C. ROUTE" at 12263.25,2276.47 h60
  text "V. SCORE" at 13129.25,2276.47 h60
  text "CERTIFICATION:" at 11202.25,2139.47 h60
  text "MATERIALS AND WORKMANSHIP FOR ALL PCBS" at 11927.25,2139.47 h60
  text "TO MEET OR EXCEED THE REQUIREMENTS OF:" at 11927.25,2041.47 h60
  text "X" at 11553.76,1904.97 h60
  text "ANSI IPC-A-600F CLASS ->" at 11692.76,1904.97 h60
  text "X" at 13331.81,1904.97 h60
  text "2" at 13450.76,1904.97 h60
  text "1" at 13135.76,1903.47 h60
  text "3" at 13804.76,1903.47 h60
  text "X" at 11555.81,1745.47 h60
  text "UL 94V-0" at 11692.76,1745.47 h60
  text "X" at 12367.81,1745.47 h60
  text "RoHS" at 12504.76,1745.47 h60
  text "OTHER" at 13149.16,1745.47 h60
  text "PER ORDER" at 13546.21,1745.47 h60
  text "ADDITIONAL REQUIREMENTS:" at 11202.25,1604.47 h60
  text "MICROSECTION:" at 11277.02,1489.47 h60
  text "YES" at 12182.76,1489.47 h60
  text "REQUIRED" at 13044.25,1333.33 h60
  text "BARE BOARD ELEC. TEST:" at 11277.02,1330.47 h60
  text "NONE" at 12582.76,1330.47 h60
  text "X" at 12917.25,1330.47 h60
  text "PER ORDER" at 13636.25,1330.47 h60
  text "MANUFACTURER'S UL:" at 11277.02,1173.47 h60
  text "RAIL" at 12442.76,1169.19 h60
  text "METAL" at 12934.57,1169.19 h60
  text "X" at 13309.79,1168.83 h60
  text "SILK" at 13446.25,1169.19 h60
  text "VIA`S TO BE TENTED:" at 11256.79,981.83 h60
  text "Refer Note" at 12161.79,981.83 h60
M11 Gerber Information:
  lines w10: -427.21,-964.33 6172.79,-964.33 ; -427.21,-761 6174.79,-761 ; -427.21,-557.67 -427.21,-1167.67 3577.79,-1167.67 6174.79,-1167.67 6174.79,-557.67 -426.71,-557.67 -426.71,-1167.67 1148.79,-1167.67 ; 2037.79,-1167.67 2037.79,-557.67 ; 3304.79,-761 3304.79,-557.67 ; 4144.79,-761 4144.79,-557.67 ; 4766.79,-1174.17 4766.79,-971.33
  text "ALL ARTWORK VIEWED FROM TOP SIDE" at -363.71,-689.83 h60
  text "BOARD #:" at 2112.79,-689.83 h60
  text ".PRJ_Number" at 2658.29,-689.83 h60
  text "REV:" at 3502.79,-689.83 h60
  text ".PCB_Rev" at 3794.29,-689.83 h60
  text "SVN REV:" at 4340.79,-689.83 h60
  text ".VersionControl_RevNumber" at 4846.79,-689.83 h60
  text "LAYER NAME =" at -363.71,-892.66 h60
  text "TID #:" at 2112.79,-893.17 h60
  text ".TID" at 2658.29,-893.17 h60
  text "PLOT NAME =" at -363.71,-1098.5 h60
  text ".plot_File_Name" at 441.79,-1098.5 h60
  text "GENERATED    :" at 2114.79,-1098.5 h60
  text ".Print_Date" at 2984.29,-1098.5 h60
  text ".Print_Time" at 3713.29,-1098.5 h60
  text "TEXAS INSTRUMENTS" at 4977.79,-1098.5 h60
M12 Stackup:
  drawing of 191 lines, arcs and shapes, not listed
  text "Layer" at 9598.46,7753.95 h60
  text "Name" at 10008.37,7753.95 h60
  text "Material" at 10938.12,7753.95 h60
  text "Thickness" at 11797.89,7753.95 h60
  text "Constant" at 12447.72,7753.95 h60
  text "Board Layer Stack" at 13017.58,7753.95 h60
  text "1" at 9598.46,7633.95 h60
  text "Top Overlay" at 10008.37,7633.95 h60
  text "2" at 9598.46,7513.95 h60
  text "Top Solder" at 10008.37,7513.95 h60
  text "Solder Resist" at 10938.12,7513.95 h60
  text "0.40mil" at 11797.89,7513.95 h60
  text "3.5" at 12447.72,7513.95 h60
  text "3" at 9598.46,7393.95 h60
  text "Top Layer" at 10008.37,7393.95 h60
  text "Copper" at 10938.12,7393.95 h60
  text "2.80mil" at 11797.89,7393.95 h60
  text "4" at 9598.46,7273.95 h60
  text "Dielectric1" at 10008.37,7273.95 h60
  text "FR-4 High Tg" at 10938.12,7273.95 h60
  text "59.00mil" at 11797.89,7273.95 h60
  text "4.8" at 12447.72,7273.95 h60
  text "5" at 9598.46,7153.95 h60
  text "Bottom Layer" at 10008.37,7153.95 h60
  text "Copper" at 10938.12,7153.95 h60
  text "2.80mil" at 11797.89,7153.95 h60
  text "6" at 9598.46,7033.95 h60
  text "Bottom Solder" at 10008.37,7033.95 h60
  text "Solder Resist" at 10938.12,7033.95 h60
  text "0.40mil" at 11797.89,7033.95 h60
  text "3.5" at 12447.72,7033.95 h60
  text "7" at 9598.46,6913.95 h60
  text "Bottom Overlay" at 10008.37,6913.95 h60
M13 Component Bodies Top:
  text ".Layer_Name" at 441.79,-892.66 h60
M14 Component Bodies Bottom:
  text ".Layer_Name" at 441.79,-892.66 h60
M15 Courtyards Top:
  text ".Layer_Name" at 441.79,-892.66 h60
M16 Courtyards Bottom:
  text ".Layer_Name" at 441.79,-892.66 h60
Drill Drawing:
  drawing of 167 lines, arcs and shapes, not listed
  text "Symbol" at 7555.01,5307.29 h96
  text "Hit Count" at 7931.28,5307.29 h96
  text "Finished Hole Size" at 8381.39,5307.29 h96
  text "Plated" at 9187,5307.29 h96
  text "Physical Length" at 9517.36,5307.29 h96
  text "Rout Path Length" at 10288.99,5307.29 h96
  text "THIS IS NOT AN IMPEDANCE CONTROL BOARD" at 7508.24,5253.39 h60
  text "16" at 7931.28,5141.32 h80
  text "10.00mil (0.254mm)" at 8381.39,5141.32 h80
  text "PTH" at 9187,5141.32 h80
  text "-" at 9517.36,5141.32 h80
  text "-" at 10288.99,5141.32 h80
  text "C" at 7523.56,5131.34 h73.76
  text "2" at 7931.28,4975.36 h80
  text "10.00mil (0.254mm)" at 8381.39,4975.36 h80
  text "NPTH" at 9187,4975.36 h80
  text "160.00mil (4.064mm)" at 9517.36,4975.36 h80
  text "150.00mil (3.810mm)" at 10288.99,4975.36 h80
  text "1" at 7931.28,4809.4 h80
  text "10.00mil (0.254mm)" at 8381.39,4809.4 h80
  text "NPTH" at 9187,4809.4 h80
  text "200.00mil (5.080mm)" at 9517.36,4809.4 h80
  text "190.00mil (4.826mm)" at 10288.99,4809.4 h80
  text "A" at 7523.56,4799.41 h73.76
  text "2" at 7931.28,4643.44 h80
  text "12.00mil (0.305mm)" at 8381.39,4643.44 h80
  text "PTH" at 9187,4643.44 h80
  text "-" at 9517.36,4643.44 h80
  text "-" at 10288.99,4643.44 h80
  text "\" at 7523.56,4479.78 h73.76
  text "109" at 7931.28,4477.47 h80
  text "15.00mil (0.381mm)" at 8381.39,4477.47 h80
  text "PTH" at 9187,4477.47 h80
  text "-" at 9517.36,4477.47 h80
  text "-" at 10288.99,4477.47 h80
  text "8" at 7931.28,4311.51 h80
  text "25.59mil (0.650mm)" at 8381.39,4311.51 h80
  text "PTH" at 9187,4311.51 h80
  text "-" at 9517.36,4311.51 h80
  text "-" at 10288.99,4311.51 h80
  text "2" at 7931.28,4145.55 h80
  text "29.53mil (0.750mm)" at 8381.39,4145.55 h80
  text "PTH" at 9187,4145.55 h80
  text "-" at 9517.36,4145.55 h80
  text "-" at 10288.99,4145.55 h80
  text "P" at 7523.56,4135.56 h73.76
  text "2" at 7931.28,3979.59 h80
  text "31.00mil (0.787mm)" at 8381.39,3979.59 h80
  text "PTH" at 9187,3979.59 h80
  text "-" at 9517.36,3979.59 h80
  text "-" at 10288.99,3979.59 h80
  text "14" at 7931.28,3813.62 h80
  text "33.47mil (0.850mm)" at 8381.39,3813.62 h80
  text "PTH" at 9187,3813.62 h80
  text "-" at 9517.36,3813.62 h80
  text "-" at 10288.99,3813.62 h80
  text "10" at 7931.28,3647.66 h80
  text "35.43mil (0.900mm)" at 8381.39,3647.66 h80
  text "PTH" at 9187,3647.66 h80
  text "-" at 9517.36,3647.66 h80
  text "-" at 10288.99,3647.66 h80
  text "8" at 7931.28,3481.7 h80
  text "39.37mil (1.000mm)" at 8381.39,3481.7 h80
  text "PTH" at 9187,3481.7 h80
  text "-" at 9517.36,3481.7 h80
  text "-" at 10288.99,3481.7 h80
  text "G" at 7523.56,3471.71 h73.76
  text "5" at 7931.28,3315.74 h80
  text "40.00mil (1.016mm)" at 8381.39,3315.74 h80
  text "PTH" at 9187,3315.74 h80
  text "-" at 9517.36,3315.74 h80
  text "-" at 10288.99,3315.74 h80
  text "10" at 7931.28,3149.77 h80
  text "41.34mil (1.050mm)" at 8381.39,3149.77 h80
  text "PTH" at 9187,3149.77 h80
  text "-" at 9517.36,3149.77 h80
  text "-" at 10288.99,3149.77 h80
  text "D" at 7523.56,3139.79 h73.76
  text "2" at 7931.28,2983.81 h80
  text "43.31mil (1.100mm)" at 8381.39,2983.81 h80
  text "PTH" at 9187,2983.81 h80
  text "-" at 9517.36,2983.81 h80
  text "-" at 10288.99,2983.81 h80
  text "[" at 7535.85,2973.82 h73.76
  text "4" at 7931.28,2817.85 h80
  text "46.06mil (1.170mm)" at 8381.39,2817.85 h80
  text "PTH" at 9187,2817.85 h80
  text "-" at 9517.36,2817.85 h80
  text "-" at 10288.99,2817.85 h80
  text "4" at 7931.28,2651.89 h80
  text "47.00mil (1.194mm)" at 8381.39,2651.89 h80
  text "PTH" at 9187,2651.89 h80
  text "-" at 9517.36,2651.89 h80
  text "-" at 10288.99,2651.89 h80
  text "B" at 7523.56,2641.9 h73.76
  text "16" at 7931.28,2485.92 h80
  text "47.24mil (1.200mm)" at 8381.39,2485.92 h80
  text "PTH" at 9187,2485.92 h80
  text "-" at 9517.36,2485.92 h80
  text "-" at 10288.99,2485.92 h80
  text "K" at 7523.56,2475.94 h73.76
  text "18" at 7931.28,2319.96 h80
  text "50.00mil (1.270mm)" at 8381.39,2319.96 h80
  text "PTH" at 9187,2319.96 h80
  text "-" at 9517.36,2319.96 h80
  text "-" at 10288.99,2319.96 h80
  text "2" at 7931.28,2154 h80
  text "51.18mil (1.300mm)" at 8381.39,2154 h80
  text "PTH" at 9187,2154 h80
  text "-" at 9517.36,2154 h80
  text "-" at 10288.99,2154 h80
  text "4" at 7931.28,1988.04 h80
  text "59.06mil (1.500mm)" at 8381.39,1988.04 h80
  text "PTH" at 9187,1988.04 h80
  text "-" at 9517.36,1988.04 h80
  text "-" at 10288.99,1988.04 h80
  text "N" at 7523.56,1978.05 h73.76
  text "9" at 7931.28,1822.08 h80
  text "62.99mil (1.600mm)" at 8381.39,1822.08 h80
  text "PTH" at 9187,1822.08 h80
  text "-" at 9517.36,1822.08 h80
  text "-" at 10288.99,1822.08 h80
  text "3" at 7931.28,1656.11 h80
  text "70.08mil (1.780mm)" at 8381.39,1656.11 h80
  text "PTH" at 9187,1656.11 h80
  text "-" at 9517.36,1656.11 h80
  text "-" at 10288.99,1656.11 h80
  text "O" at 7523.56,1646.12 h73.76
  text "4" at 7931.28,1490.15 h80
  text "110.24mil (2.800mm)" at 8381.39,1490.15 h80
  text "PTH" at 9187,1490.15 h80
  text "-" at 9517.36,1490.15 h80
  text "-" at 10288.99,1490.15 h80
  text "4" at 7931.28,1324.19 h80
  text "118.11mil (3.000mm)" at 8381.39,1324.19 h80
  text "PTH" at 9187,1324.19 h80
  text "-" at 9517.36,1324.19 h80
  text "-" at 10288.99,1324.19 h80
  text "6" at 7931.28,1158.23 h80
  text "125.00mil (3.175mm)" at 8381.39,1158.23 h80
  text "PTH" at 9187,1158.23 h80
  text "-" at 9517.36,1158.23 h80
  text "-" at 10288.99,1158.23 h80
  text "265 Total" at 7931.28,992.26 h80
  text "Slot definitions :" at 7555.01,876.09 h80
  text "Rout Path Length" at 8101.12,876.09 h80
  text "= Calculated from tool start centre position to tool end centre position." at 8697.93,876.09 h80
  text "Physical Length" at 8101.12,809.7 h80
  text "= Rout Path Length + Tool Size = Slot length as defined in the PCB layout" at 8646.3,809.7 h80
  text "DRILL TABLE" at 7974.85,619.23 h60
  text "FOR 7.874MIL DRILL +0/-7.874MIL" at 7974.85,510.23 h60
  text "FOR 15MIL DRILL +0/-15MIL" at 7972.85,412.23 h60
  text "FOR PTH DRILL +/-3MIL" at 7972.85,304.23 h60
  text "FOR NPTH DRILL +/-2MIL" at 7960.2,193.83 h60
  text ".Layer_Name" at 441.79,-892.66 h60
M17 Embedded Cavity:
  text ".Layer_Name" at 441.79,-892.66 h60
M18 Embedded Assembly:
  text ".Layer_Name" at 441.79,-892.66 h60
M19 Embedded Keepout:
  text ".Layer_Name" at 441.79,-892.66 h60

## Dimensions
0,4330.71 to 7283.46,4330.71 on M2 Board Dimensions
0,0 to 0,4330.71 on M2 Board Dimensions
-135.21,-434.17 to 864.79,-434.17 on M2 Board Dimensions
